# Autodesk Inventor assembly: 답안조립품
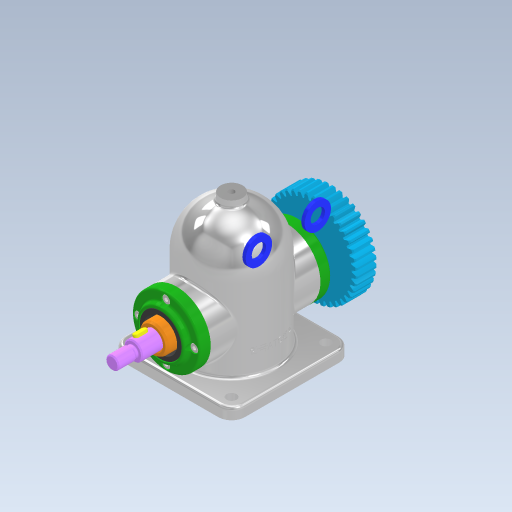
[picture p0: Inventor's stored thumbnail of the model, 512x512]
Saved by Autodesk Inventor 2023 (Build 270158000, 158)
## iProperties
Created: 2025-04
Part Number: 답안조립품
Document SubType Name: Assembly
Designer: Admin
Author: Admin
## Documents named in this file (11)
- C:\Users\Admin\Desktop\750406V1004\답안조립품.iam
- C:\Users\Admin\Desktop\750406V1004\본체.ipt
- C:\Users\Admin\Desktop\750406V1004\깊은 홈 볼 베어링 6203.ipt
- C:\Users\Admin\Desktop\750406V1004\축.ipt
- C:\Users\Admin\Desktop\750406V1004\커버.ipt
- C:\Users\Admin\Desktop\750406V1004\오일 실 26 38 8.ipt
- C:\Users\Admin\Desktop\750406V1004\6각 구멍붙이 볼트 M4x12.ipt
- C:\Users\Admin\Desktop\750406V1004\칼라.ipt
- C:\Users\Admin\Desktop\750406V1004\평와셔 M12.ipt
- C:\Users\Admin\Desktop\750406V1004\평행 키 5x5x12.ipt
- C:\Users\Admin\Desktop\750406V1004\스퍼기어.ipt
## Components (8 placed, 1 different names)
1. 6각 구멍붙이 볼트 M4x12:1
2. 6각 구멍붙이 볼트 M4x12:2
3. 6각 구멍붙이 볼트 M4x12:3
4. 6각 구멍붙이 볼트 M4x12:4
5. 6각 구멍붙이 볼트 M4x12:5
6. 6각 구멍붙이 볼트 M4x12:6
7. 6각 구멍붙이 볼트 M4x12:7
8. 6각 구멍붙이 볼트 M4x12:8
